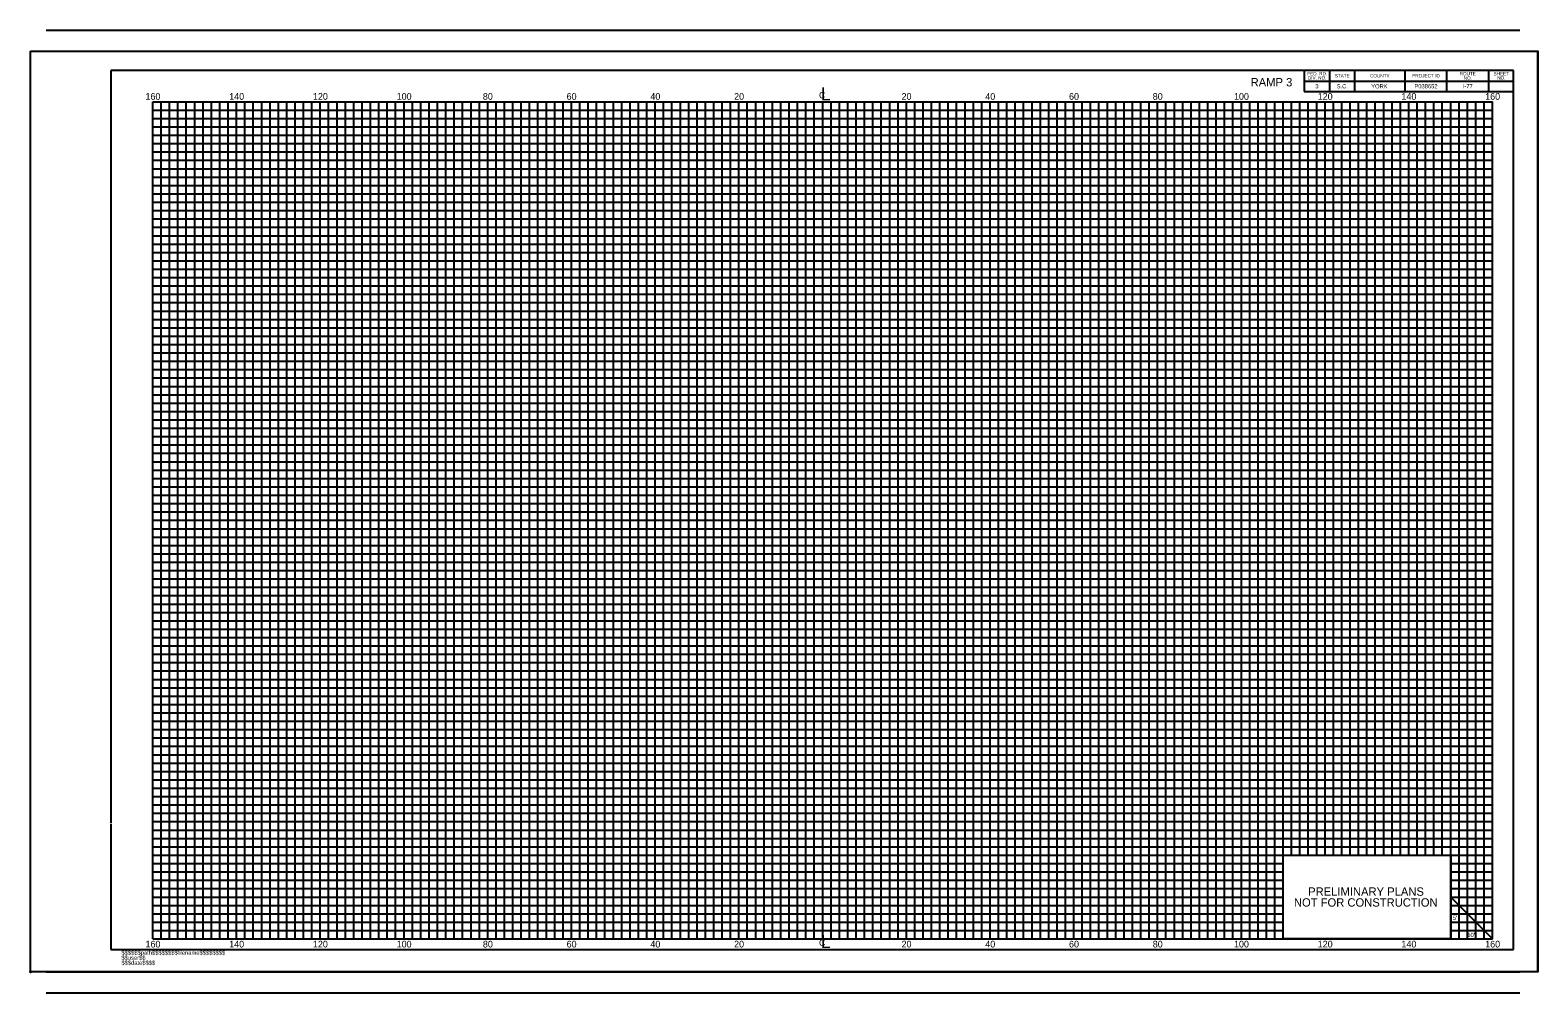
# Model space of a CAD drawing. Extents: x -15 to 165, y -6 to 109.
import ezdxf

# ---------------------------------------------------------------- set-up
doc = ezdxf.new("R2010")
doc.units = 0
for name, color, linetype in [('RD_DDB_StaTX', 7, 'Continuous'), ('RD_SHT_Bndy', 7, 'Continuous'), ('RD_SHT_ID', 7, 'Continuous'), ('RD_SHT_IplotShp', 7, 'Continuous'), ('RD_SHT_MjGrid_XS', 7, 'Continuous'), ('RD_SHT_MnGrid_XS', 7, 'Continuous'), ('RD_SHT_Snap', 7, 'Continuous'), ('RD_SHT_TX', 7, 'Continuous')]:
    doc.layers.add(name, color=color, linetype=linetype)

msp = doc.modelspace()

# ---------------------------------------------------------------- linework, layer by layer
at = {"layer": 'RD_SHT_Bndy'}
for p, q in [((-12.73, 108.55), (163.27, 108.55)), ((-12.73, 106.05), (163.27, 106.05)), ((-5, 103.72), (-5, 13.81)), ((162.51, 103.72), (-5, 103.72)), ((137.51, 103.72), (137.51, 101.22)), ((140.51, 103.72), (140.51, 101.22)), ((143.51, 103.72), (143.51, 101.22)), ((149.51, 103.72), (149.51, 101.22)), ((154.51, 103.72), (154.51, 101.22)), ((159.51, 103.72), (159.51, 101.22)), ((162.51, -1.28), (162.51, 103.72)), ((137.51, 102.47), (162.51, 102.47)), ((137.51, 101.22), (162.51, 101.22)), ((-5, 13.72), (-5, -1.28)), ((139.95, 5), (139.95, 5)), ((145, 5), (145, 5)), ((-5, -1.28), (162.51, -1.28)), ((-12.73, -3.95), (163.27, -3.95)), ((-12.73, -6.45), (163.27, -6.45))]:
    msp.add_line(p, q, dxfattribs=at)
msp.add_lwpolyline([(135, 10), (155, 10), (155, 0), (135, 0)], close=True, dxfattribs=at)
at = {"layer": 'RD_SHT_IplotShp'}
msp.add_lwpolyline([(-14.59, 106.05), (165.41, 106.05), (165.41, -3.95), (-14.59, -3.95)], close=True, dxfattribs=at)
at = {"layer": 'RD_SHT_MjGrid_XS'}
for p, q in [((0, 100), (160, 100)), ((0, 0), (0, 100)), ((5, 0), (5, 100)), ((10, 0), (10, 100)), ((15, 0), (15, 100)), ((20, 0), (20, 100)), ((25, 0), (25, 100)), ((30, 0), (30, 100)), ((35, 0), (35, 100)), ((40, 0), (40, 100)), ((45, 0), (45, 100)), ((50, 0), (50, 100)), ((55, 0), (55, 100)), ((60, 0), (60, 100)), ((65, 0), (65, 100)), ((70, 0), (70, 100)), ((75, 0), (75, 100)), ((80, 0), (80, 100)), ((85, 0), (85, 100)), ((90, 0), (90, 100)), ((95, 0), (95, 100)), ((100, 0), (100, 100)), ((105, 0), (105, 100)), ((110, 0), (110, 100)), ((115, 0), (115, 100)), ((120, 0), (120, 100)), ((125, 0), (125, 100)), ((130, 0), (130, 100)), ((135, 0), (135, 100)), ((140, 10), (140, 100)), ((145, 10), (145, 100)), ((150, 10), (150, 100)), ((155, 0), (155, 100)), ((160, 0), (160, 100)), ((0, 95), (160, 95)), ((0, 90), (160, 90)), ((0, 85), (160, 85)), ((0, 80), (160, 80)), ((0, 75), (160, 75)), ((0, 70), (160, 70)), ((0, 65), (160, 65)), ((0, 60), (160, 60)), ((0, 55), (160, 55)), ((0, 50), (160, 50)), ((0, 45), (160, 45)), ((0, 40), (160, 40)), ((0, 35), (160, 35)), ((0, 30), (160, 30)), ((0, 25), (160, 25)), ((0, 20), (160, 20)), ((0, 15), (160, 15)), ((0, 10), (160, 10)), ((0, 5), (135, 5)), ((155, 5), (160, 0)), ((155, 5), (160, 5)), ((0, 0), (160, 0))]:
    msp.add_line(p, q, dxfattribs=at)
at = {"layer": 'RD_SHT_MnGrid_XS'}
for p, q in [((1, 0), (1, 100)), ((2, 0), (2, 100)), ((3, 0), (3, 100)), ((4, 0), (4, 100)), ((6, 0), (6, 100)), ((7, 0), (7, 100)), ((8, 0), (8, 100)), ((9, 0), (9, 100)), ((11, 0), (11, 100)), ((12, 0), (12, 100)), ((13, 0), (13, 100)), ((14, 0), (14, 100)), ((16, 0), (16, 100)), ((17, 0), (17, 100)), ((18, 0), (18, 100)), ((19, 0), (19, 100)), ((21, 0), (21, 100)), ((22, 0), (22, 100)), ((23, 0), (23, 100)), ((24, 0), (24, 100)), ((26, 0), (26, 100)), ((27, 0), (27, 100)), ((28, 0), (28, 100)), ((29, 0), (29, 100)), ((31, 0), (31, 100)), ((32, 0), (32, 100)), ((33, 0), (33, 100)), ((34, 0), (34, 100)), ((36, 0), (36, 100)), ((37, 0), (37, 100)), ((38, 0), (38, 100)), ((39, 0), (39, 100)), ((41, 0), (41, 100)), ((42, 0), (42, 100)), ((43, 0), (43, 100)), ((44, 0), (44, 100)), ((46, 0), (46, 100)), ((47, 0), (47, 100)), ((48, 0), (48, 100)), ((49, 0), (49, 100)), ((51, 0), (51, 100)), ((52, 0), (52, 100)), ((53, 0), (53, 100)), ((54, 0), (54, 100)), ((56, 0), (56, 100)), ((57, 0), (57, 100)), ((58, 0), (58, 100)), ((59, 0), (59, 100)), ((61, 0), (61, 100)), ((62, 0), (62, 100)), ((63, 0), (63, 100)), ((64, 0), (64, 100)), ((66, 0), (66, 100)), ((67, 0), (67, 100)), ((68, 0), (68, 100)), ((69, 0), (69, 100)), ((71, 0), (71, 100)), ((72, 0), (72, 100)), ((73, 0), (73, 100)), ((74, 0), (74, 100)), ((76, 0), (76, 100)), ((77, 0), (77, 100)), ((78, 0), (78, 100)), ((79, 0), (79, 100)), ((81, 0), (81, 100)), ((82, 0), (82, 100)), ((83, 0), (83, 100)), ((84, 0), (84, 100)), ((86, 0), (86, 100)), ((87, 0), (87, 100)), ((88, 0), (88, 100)), ((89, 0), (89, 100)), ((91, 0), (91, 100)), ((92, 0), (92, 100)), ((93, 0), (93, 100)), ((94, 0), (94, 100)), ((96, 0), (96, 100)), ((97, 0), (97, 100)), ((98, 0), (98, 100)), ((99, 0), (99, 100)), ((101, 0), (101, 100)), ((102, 0), (102, 100)), ((103, 0), (103, 100)), ((104, 0), (104, 100)), ((106, 0), (106, 100)), ((107, 0), (107, 100)), ((108, 0), (108, 100)), ((109, 0), (109, 100)), ((111, 0), (111, 100)), ((112, 0), (112, 100)), ((113, 0), (113, 100)), ((114, 0), (114, 100)), ((116, 0), (116, 100)), ((117, 0), (117, 100)), ((118, 0), (118, 100)), ((119, 0), (119, 100)), ((121, 0), (121, 100)), ((122, 0), (122, 100)), ((123, 0), (123, 100)), ((124, 0), (124, 100)), ((126, 0), (126, 100)), ((127, 0), (127, 100)), ((128, 0), (128, 100)), ((129, 0), (129, 100)), ((131, 0), (131, 100)), ((132, 0), (132, 100)), ((133, 0), (133, 100)), ((134, 0), (134, 100)), ((136, 10), (136, 100)), ((137, 10), (137, 100)), ((138, 10), (138, 100)), ((139, 10), (139, 100)), ((141, 10), (141, 100)), ((142, 10), (142, 100)), ((143, 10), (143, 100)), ((144, 10), (144, 100)), ((146, 10), (146, 100)), ((147, 10), (147, 100)), ((148, 10), (148, 100)), ((149, 10), (149, 100)), ((151, 10), (151, 100)), ((152, 10), (152, 100)), ((153, 10), (153, 100)), ((154, 10), (154, 100)), ((156, 0), (156, 100)), ((157, 0), (157, 100)), ((158, 0), (158, 100)), ((159, 0), (159, 100)), ((0, 99), (160, 99)), ((0, 98), (160, 98)), ((0, 97), (160, 97)), ((0, 96), (160, 96)), ((0, 94), (160, 94)), ((0, 93), (160, 93)), ((0, 92), (160, 92)), ((0, 91), (160, 91)), ((0, 89), (160, 89)), ((0, 88), (160, 88)), ((0, 87), (160, 87)), ((0, 86), (160, 86)), ((0, 84), (160, 84)), ((0, 83), (160, 83)), ((0, 82), (160, 82)), ((0, 81), (160, 81)), ((0, 79), (160, 79)), ((0, 78), (160, 78)), ((0, 77), (160, 77)), ((0, 76), (160, 76)), ((0, 74), (160, 74)), ((0, 73), (160, 73)), ((0, 72), (160, 72)), ((0, 71), (160, 71)), ((0, 69), (160, 69)), ((0, 68), (160, 68)), ((0, 67), (160, 67)), ((0, 66), (160, 66)), ((0, 64), (160, 64)), ((0, 63), (160, 63)), ((0, 62), (160, 62)), ((0, 61), (160, 61)), ((0, 59), (160, 59)), ((0, 58), (160, 58)), ((0, 57), (160, 57)), ((0, 56), (160, 56)), ((0, 54), (160, 54)), ((0, 53), (160, 53)), ((0, 52), (160, 52)), ((0, 51), (160, 51)), ((0, 49), (160, 49)), ((0, 48), (160, 48)), ((0, 47), (160, 47)), ((0, 46), (160, 46)), ((0, 44), (160, 44)), ((0, 43), (160, 43)), ((0, 42), (160, 42)), ((0, 41), (160, 41)), ((0, 39), (160, 39)), ((0, 38), (160, 38)), ((0, 37), (160, 37)), ((0, 36), (160, 36)), ((0, 34), (160, 34)), ((0, 33), (160, 33)), ((0, 32), (160, 32)), ((0, 31), (160, 31)), ((0, 29), (160, 29)), ((0, 28), (160, 28)), ((0, 27), (160, 27)), ((0, 26), (160, 26)), ((0, 24), (160, 24)), ((0, 23), (160, 23)), ((0, 22), (160, 22)), ((0, 21), (160, 21)), ((0, 21), (160, 21)), ((0, 19), (160, 19)), ((0, 18), (160, 18)), ((0, 17), (160, 17)), ((0, 16), (160, 16)), ((0, 14), (160, 14)), ((0, 13), (160, 13)), ((0, 12), (160, 12)), ((0, 11), (160, 11)), ((0, 9), (135, 9)), ((0, 8), (135, 8)), ((155, 9), (160, 9)), ((155, 8), (160, 8)), ((0, 7), (135, 7)), ((0, 6), (135, 6)), ((155, 7), (160, 7)), ((155, 6), (160, 6)), ((0, 4), (135, 4)), ((155, 4), (160, 4)), ((0, 3), (135, 3)), ((0, 2), (135, 2)), ((155, 3), (160, 3)), ((155, 2), (160, 2)), ((0, 1), (135, 1)), ((155, 1), (160, 1))]:
    msp.add_line(p, q, dxfattribs=at)
at = {"layer": 'RD_SHT_Snap'}
for p, q in [((-14.59, -3.95), (-14.59, 106.05)), ((165.41, -3.95), (165.41, 106.05))]:
    msp.add_line(p, q, dxfattribs=at)
msp.add_circle((-14.59, -3.95), 0.0607, dxfattribs=at)

# ---------------------------------------------------------------- texts
at = {"layer": 'RD_DDB_StaTX'}
for s, height, p in [('160', 0.8, (-0.88, 100.23)), ('140', 0.8, (9.12, 100.23)), ('120', 0.8, (19.12, 100.23)), ('100', 0.8, (29.12, 100.23)), ('80', 0.8, (39.42, 100.23)), ('60', 0.8, (49.42, 100.23)), ('40', 0.8, (59.42, 100.23)), ('20', 0.8, (69.42, 100.23)), ('C', 0.773, (79.56, 100.4)), ('L', 1.55, (79.79, 100.16)), ('20', 0.8, (89.42, 100.23)), ('40', 0.8, (99.42, 100.23)), ('60', 0.8, (109.42, 100.23)), ('80', 0.8, (119.42, 100.23)), ('100', 0.8, (129.12, 100.23)), ('120', 0.8, (139.12, 100.23)), ('140', 0.8, (149.12, 100.23)), ('160', 0.8, (159.12, 100.23)), ('L', 1.55, (79.79, -1.09)), ('160', 0.8, (-0.88, -1.03)), ('140', 0.8, (9.12, -1.03)), ('120', 0.8, (19.12, -1.03)), ('100', 0.8, (29.12, -1.03)), ('80', 0.8, (39.42, -1.03)), ('60', 0.8, (49.42, -1.03)), ('40', 0.8, (59.42, -1.03)), ('20', 0.8, (69.42, -1.03)), ('C', 0.773, (79.56, -0.85)), ('20', 0.8, (89.42, -1.03)), ('40', 0.8, (99.42, -1.03)), ('60', 0.8, (109.42, -1.03)), ('80', 0.8, (119.42, -1.03)), ('100', 0.8, (129.12, -1.03)), ('120', 0.8, (139.12, -1.03)), ('140', 0.8, (149.12, -1.03)), ('160', 0.8, (159.12, -1.03))]:
    msp.add_text(s, height=height, dxfattribs=at).set_placement(p)
at = {"layer": 'RD_SHT_ID'}
for s, p in [('$$$$$$path$$$$$$$$filename$$$$$$$$', (-3.75, -1.9)), ('$$user$$', (-3.75, -2.5)), ('$$$date$$$$', (-3.75, -3.1))]:
    msp.add_text(s, height=0.5, rotation=360, dxfattribs=at).set_placement(p)
at = {"layer": 'RD_SHT_TX'}
for s, height, p in [('RAMP 3', 1, (131.11, 101.83)), ('FED. RD.', 0.4, (137.88, 103.15)), ('DIV. NO.', 0.4, (137.95, 102.65)), ('STATE', 0.4, (141.15, 102.9)), ('COUNTY', 0.4, (145.37, 102.9)), ('PROJECT ID', 0.4, (150.41, 102.9)), ('ROUTE', 0.4, (156.07, 103.15)), ('NO.', 0.4, (156.56, 102.63)), ('SHEET', 0.4, (160.12, 103.15)), ('NO.', 0.4, (160.56, 102.65)), ('3', 0.5, (138.84, 101.6)), ('S.C.', 0.5, (141.39, 101.6)), ('YORK', 0.5, (145.51, 101.6)), ('P038652', 0.5, (150.67, 101.6)), ('I-77', 0.5, (156.44, 101.6)), ('PRELIMINARY PLANS', 1, (137.98, 5.15)), ('NOT FOR CONSTRUCTION', 1, (136.28, 3.85)), ("5'", 0.512, (155.26, 2.26)), ("10'", 0.512, (156.97, 0.21))]:
    msp.add_text(s, height=height, dxfattribs=at).set_placement(p)

doc.saveas('drawing.dxf')
